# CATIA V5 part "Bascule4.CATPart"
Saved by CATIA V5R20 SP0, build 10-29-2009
Part number: Bascule4
Bounding box of the stored display mesh (mm): x -0.3 to 0, y 8.009 to 72, z 35.504 to 54.496
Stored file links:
  C:\Users\J\IAO_2012_jgossard\Bascule4.CATPart
  C:\Users\J\IAO_2012_jgossard\jgossard.CATProduct
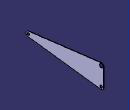
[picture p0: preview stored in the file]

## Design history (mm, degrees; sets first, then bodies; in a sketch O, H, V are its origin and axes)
Set1
  Plane1 "Plan_ref": linked copy from another document
  Point1 "Point_C": linked copy from another document
  Point2 "Point_D": linked copy from another document
  Point3 "Point_E": linked copy from another document
Body1 (main body)
  Sketch1 on Plane1, origin (0, 0, 0), H (0, 1, 0), V (0, 0, 1)
    line L1 (9.7519, 46.9846) -> (69.7519, 54.4846)
    line L2 (9.7519, 43.0154) -> (69.7519, 35.5154)
    line L3 (72, 37.5) -> (72, 52.5)
    arc A1 centre (70, 37.5) radius 2 from (72, 37.5) to (69.7519, 35.5154) cw
    point P7 (70, 37.5)
    point P8 (72, 37.5)
    arc A2 centre (70, 52.5) radius 2 from (72, 52.5) to (69.7519, 54.4846) ccw
    point P9 (70, 52.5)
    arc A3 centre (10, 45) radius 2 from (9.7519, 43.0154) to (9.7519, 46.9846) cw
    point P10 (10, 45)
    reference projected point E1 (10, 45) from Point1
    reference projected point E2 (70, 52.5) from Point2
    reference projected point E3 (70, 37.5) from Point3
    radius A3 = 2
    radius A2 = 2
    vertical: L3 V
    coincidence: A1 P8, P8 L3, P10 E1, P9 E2, P7 E3
    tangency: A2 L1, A3 L1, L3 A2, L3 A1, A1 L2, L2 A3
  Pad1: profile Sketch1, direction (-1, 0, 0), length 0.3
  Sketch2 on end face of Pad1, origin (-0.3, 13.4767, 34.3582), H (0, 1, 0), V (0, 0, -1)
    point P1 (-3.4767, -10.6418)
    reference projected point E1 (-3.4767, -10.6418) from Point1
    coincidence: P1 E1
  Hole1: placed by Sketch2, at (-0.3, 10, 45) direction (1, 0, 0), diameter 2, through (limit type 6)
  Sketch3 on end face of Pad1, origin (-0.3, 69.6095, 41.3113), H (0, 1, 0), V (0, 0, -1)
    point P1 (0.3905, -11.1887)
    reference projected point E1 (0.3905, -11.1887) from Point2
    coincidence: P1 E1
  Hole2: placed by Sketch3, at (-0.3, 70, 52.5) direction (1, 0, 0), diameter 3, through (limit type 6)
  Sketch4 on end face of Pad1, origin (-0.3, 68.3696, 30.4366), H (0, 1, 0), V (0, 0, -1)
    point P1 (1.6304, -7.0634)
    reference projected point E1 (1.6304, -7.0634) from Point3
    coincidence: P1 E1
  Hole3: placed by Sketch4, at (-0.3, 70, 37.5) direction (1, 0, 0), diameter 2, through (limit type 6)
